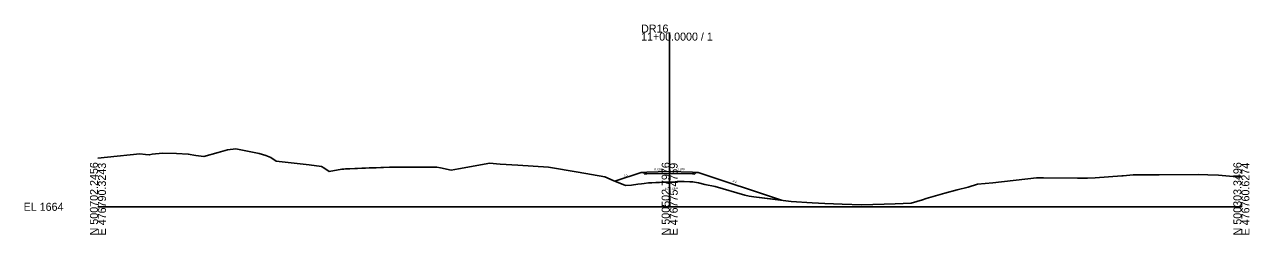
# Model space of a CAD drawing. Extents: x -26 to 403, y -10 to 1535.
# Drawn here: x -25.7 to 402.8, y 990.3 to 1063.8 of the extents above; entities that cross this region are included whole.
import ezdxf

# ---------------------------------------------------------------- set-up
doc = ezdxf.new("R2010")
doc.units = 0
for name, color, linetype in [('Exist Cross Section Cell', 7, 'Continuous'), ('Exist XS Center Line Elevation Label', 7, 'Continuous'), ('Exist XS Ground Line', 7, 'Continuous'), ('Prop XS Ditch Slope Text', 7, 'Continuous'), ('Prop XS Earthwork Shape', 7, 'Continuous'), ('Prop XS Finish Grade', 7, 'Continuous'), ('Prop XS Finish Grade Earthwork', 7, 'Continuous'), ('Prop XS Finish Grade Pavement', 7, 'Continuous'), ('Prop XS Pvmt Edge Slope', 7, 'Continuous'), ('Prop XS SE Text', 7, 'Continuous'), ('Prop XS Shoulder Borrow Shape', 7, 'Continuous'), ('Prop XS Subgrade Earthwork', 7, 'Continuous')]:
    doc.layers.add(name, color=color, linetype=linetype)

msp = doc.modelspace()

# ---------------------------------------------------------------- linework, layer by layer
at = {"layer": 'Exist Cross Section Cell'}
for p, q in [((200, 1000), (200, 1060.97)), ((0, 1000), (200, 1000)), ((200, 1000), (400, 1000))]:
    msp.add_line(p, q, dxfattribs=at)
at = {"layer": 'Exist XS Ground Line'}
msp.add_lwpolyline([(0, 1017.05), (3.34, 1017.32), (14.67, 1018.55), (16.67, 1018.27), (17.93, 1018.15), (19, 1018.39), (22.58, 1018.8), (27.51, 1018.64), (31.59, 1018.47), (34.3, 1018), (37.09, 1017.57), (42.02, 1019), (45.34, 1019.98), (48.18, 1020.32), (56.38, 1018.71), (58.76, 1017.96), (60.5, 1017.31), (62.39, 1016.02), (73.85, 1014.7), (78.25, 1014.11), (79.03, 1013.65), (80.94, 1012.41), (85.35, 1013.13), (86, 1013.23), (86.57, 1013.25), (87.17, 1013.28), (88.17, 1013.32), (89.88, 1013.39), (90.84, 1013.43), (92.3, 1013.48), (93.55, 1013.53), (94.85, 1013.59), (95.99, 1013.64), (97.35, 1013.69), (99, 1013.77), (99.9, 1013.8), (102.01, 1013.9), (102.53, 1013.91), (104.37, 1013.92), (104.9, 1013.92), (105.32, 1013.92), (107.34, 1013.93), (109.82, 1013.93), (110.49, 1013.93), (112.47, 1013.92), (114.81, 1013.92), (115.26, 1013.92), (115.71, 1013.92), (116.09, 1013.92), (117.35, 1013.92), (118.55, 1013.91), (119.88, 1013.62), (123.61, 1012.88), (126.15, 1013.35), (137.09, 1015.22), (139.46, 1014.99), (140.73, 1014.87), (146.86, 1014.53), (157.6, 1013.9), (168.02, 1012.1), (177.32, 1010.51), (180.29, 1009.19), (184.54, 1007.46), (186.63, 1007.61), (188.9, 1007.9), (190.1, 1008.08), (191.04, 1008.17), (192.63, 1008.34), (193.78, 1008.4), (195.13, 1008.48), (196.49, 1008.52), (197.63, 1008.57), (198.26, 1008.6), (198.65, 1008.62), (199.34, 1008.65), (200.13, 1008.68), (201.87, 1008.78), (202.62, 1008.82), (203.26, 1008.83), (205.13, 1008.84), (207.04, 1008.8), (207.47, 1008.8), (208, 1008.79), (210.06, 1008.34), (212.33, 1007.85), (215.89, 1007.15), (226.33, 1004.08), (227.81, 1003.73), (229.42, 1003.49), (242.5, 1001.87), (249.85, 1001.36), (254.33, 1001.19), (260.29, 1000.95), (267.2, 1000.67), (278.88, 1001.05), (284.46, 1001.23), (288.5, 1002.43), (289.77, 1002.86), (296.28, 1004.76), (300.63, 1005.94), (304.37, 1006.83), (307.73, 1007.95), (313.1, 1008.41), (328.27, 1010.14), (330.76, 1010.14), (342.64, 1009.97), (346.16, 1009.98), (348.84, 1010.17), (358.14, 1010.81), (358.68, 1010.85), (362.18, 1011.24), (368.68, 1011.17), (369.32, 1011.17), (371.28, 1011.23), (385.11, 1011.3), (388.28, 1011.24), (391.96, 1011.09), (398.36, 1010.49), (400, 1010.36)], dxfattribs=at)
at = {"layer": 'Prop XS Earthwork Shape'}
msp.add_lwpolyline([(208, 1011.49), (200, 1011.65), (192, 1011.49), (191.32, 1011.48), (190.74, 1012.06), (190, 1012), (180.87, 1008.96), (184.54, 1007.46), (186.63, 1007.61), (188.9, 1007.9), (190.1, 1008.08), (191.04, 1008.17), (192.63, 1008.34), (193.78, 1008.4), (195.13, 1008.48), (196.49, 1008.52), (197.63, 1008.57), (198.26, 1008.6), (198.65, 1008.62), (199.34, 1008.65), (200.13, 1008.68), (201.87, 1008.78), (202.62, 1008.82), (203.26, 1008.83), (205.13, 1008.84), (207.04, 1008.8), (207.47, 1008.8), (208, 1008.79), (210.06, 1008.34), (212.33, 1007.85), (215.89, 1007.15), (226.33, 1004.08), (227.81, 1003.73), (229.42, 1003.49), (239.14, 1002.29), (210, 1012), (209.26, 1012.06), (208.68, 1011.48)], close=True, dxfattribs=at)
at = {"layer": 'Prop XS Finish Grade'}
for p, q in [((192, 1012.16), (190.74, 1012.06)), ((208, 1012.16), (209.26, 1012.06))]:
    msp.add_line(p, q, dxfattribs=at)
at = {"layer": 'Prop XS Finish Grade Earthwork'}
for p, q in [((190, 1012), (180.87, 1008.96)), ((190.74, 1012.06), (190, 1012)), ((209.26, 1012.06), (210, 1012)), ((210, 1012), (239.14, 1002.29))]:
    msp.add_line(p, q, dxfattribs=at)
at = {"layer": 'Prop XS Finish Grade Pavement'}
for p, q in [((192, 1012.16), (200, 1012.32)), ((200, 1012.32), (208, 1012.16))]:
    msp.add_line(p, q, dxfattribs=at)
at = {"layer": 'Prop XS Pvmt Edge Slope'}
for p, q in [((192, 1012.16), (191.32, 1011.48)), ((208, 1012.16), (208.68, 1011.48))]:
    msp.add_line(p, q, dxfattribs=at)
at = {"layer": 'Prop XS Shoulder Borrow Shape'}
for points in [[(192, 1012.16), (190.74, 1012.06), (191.32, 1011.48)], [(208, 1012.16), (209.26, 1012.06), (208.68, 1011.48)]]:
    msp.add_lwpolyline(points, close=True, dxfattribs=at)
at = {"layer": 'Prop XS Subgrade Earthwork'}
for p, q in [((191.32, 1011.48), (190.74, 1012.06)), ((192, 1011.49), (191.32, 1011.48)), ((200, 1011.65), (192, 1011.49)), ((208, 1011.49), (200, 1011.65)), ((208, 1011.49), (208.68, 1011.48)), ((208.68, 1011.48), (209.26, 1012.06))]:
    msp.add_line(p, q, dxfattribs=at)

# ---------------------------------------------------------------- texts
at = {"layer": 'Exist Cross Section Cell'}
for s, p in [('DR16', (190, 1060.97)), ('11+00.0000 / 1', (190, 1058.17)), ('EL 1664', (-26, 998.6))]:
    msp.add_text(s, height=2.8, dxfattribs=at).set_placement(p)
for s, p in [('N 500702.2456', (0, 990)), ('E 476790.3243', (2.8, 990)), ('N 500502.7976', (200, 990)), ('E 476775.4759', (202.8, 990)), ('N 500303.3496', (400, 990)), ('E 476760.6274', (402.8, 990))]:
    msp.add_text(s, height=2.8, rotation=90, dxfattribs=at).set_placement(p)
at = {"layer": 'Exist XS Center Line Elevation Label'}
msp.add_text('1672.68', height=0.75, dxfattribs=at).set_placement((198.27, 1005.93))
at = {"layer": 'Prop XS Ditch Slope Text'}
for rotation, p in [(18.4349, (184.11, 1010.4)), (341.5651, (221.95, 1008.75))]:
    msp.add_text('3:1', height=0.75, rotation=rotation, dxfattribs=at).set_placement(p)
at = {"layer": 'Prop XS SE Text'}
for rotation, p in [(1.1458, (194.69, 1012.71)), (358.8542, (202.69, 1012.77))]:
    msp.add_text('0.020', height=0.75, rotation=rotation, dxfattribs=at).set_placement(p)

doc.saveas('drawing.dxf')
